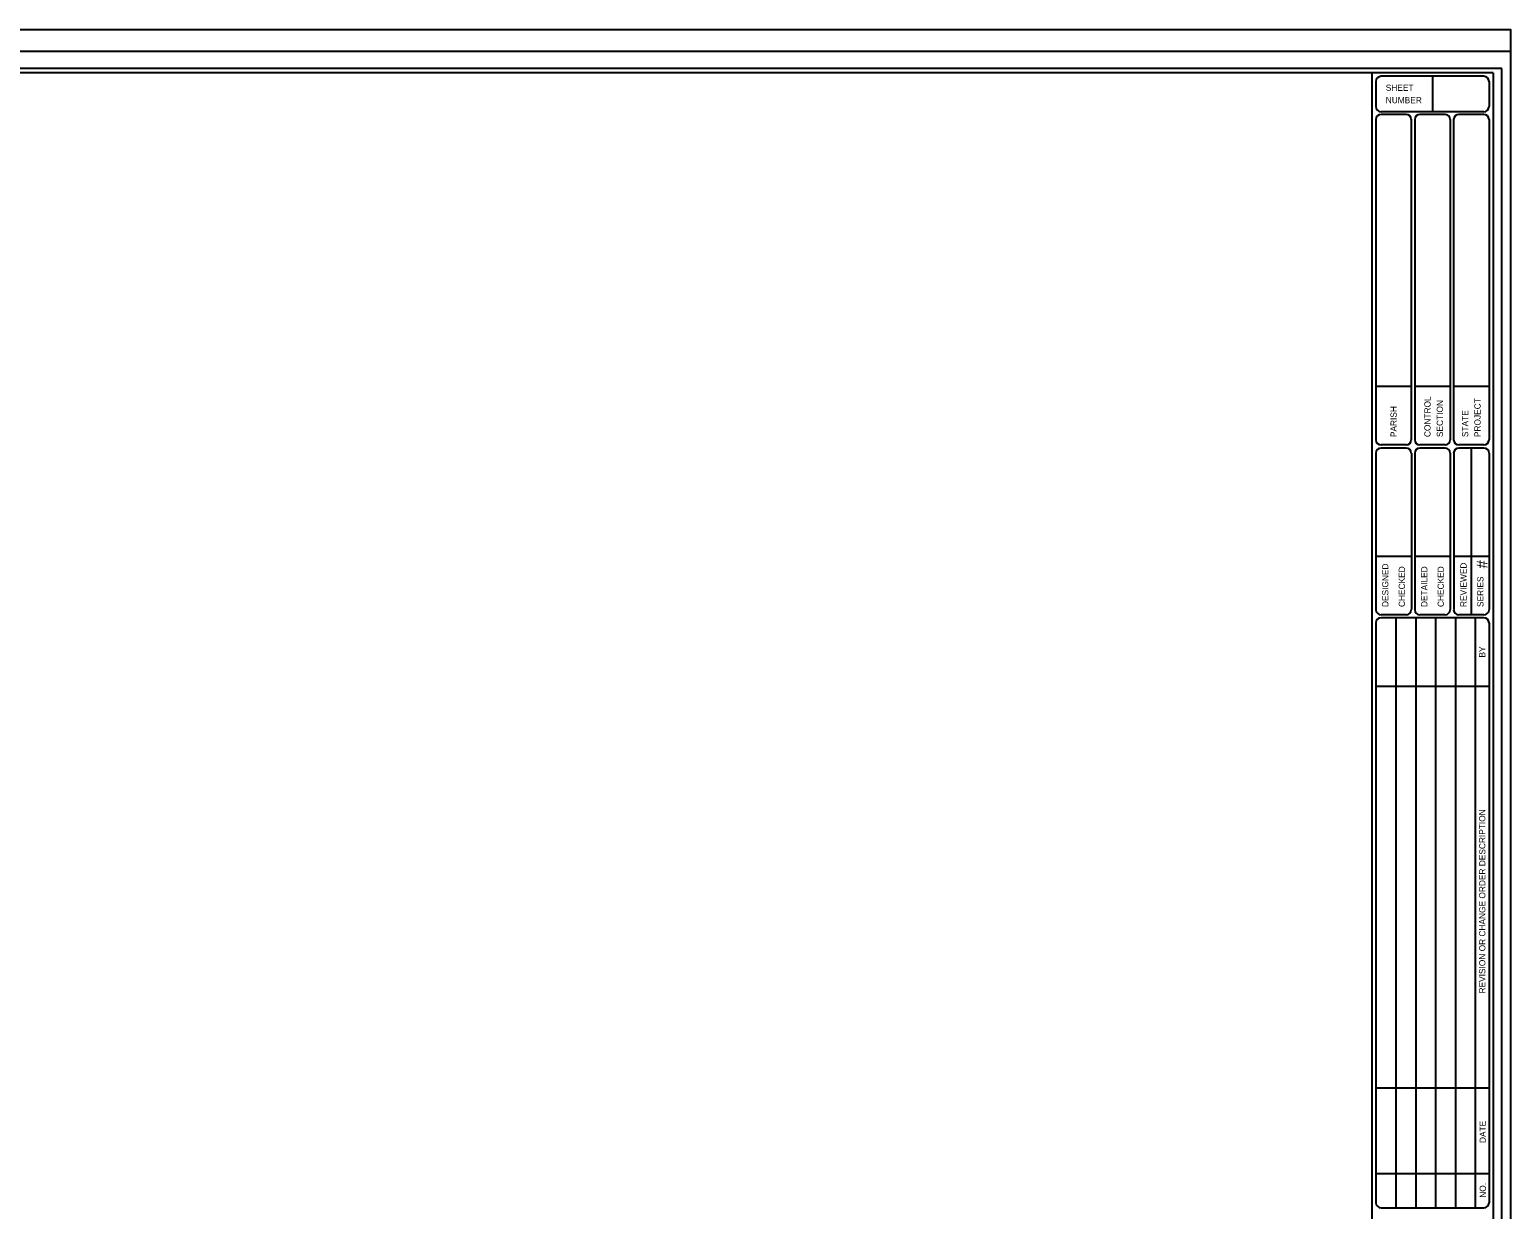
# Model space of a CAD drawing. Extents: x -2.5 to 31.7, y -0.7 to 21.7.
# Drawn here: x 14.59 to 31.7, y 7.86 to 21.5 of the extents above; entities that cross this region are included whole.
import ezdxf

# ---------------------------------------------------------------- set-up
doc = ezdxf.new("R2010")
doc.units = 0
for name, color, linetype in [('Annotation', 7, 'Continuous'), ('Plot Border', 7, 'Continuous'), ('Plot Border 2', 7, 'Continuous'), ('Sheet Border', 7, 'Continuous')]:
    doc.layers.add(name, color=color, linetype=linetype)

msp = doc.modelspace()

# ---------------------------------------------------------------- linework, layer by layer
at = {"layer": 'Plot Border'}
for points in [[(-2.3, 21.5), (31.7, 21.5), (31.7, -0.5), (-2.3, -0.5)], [(31.6, 21.05), (-1.4, 21.05), (-1.4, -0.05), (31.6, -0.05)]]:
    msp.add_lwpolyline(points, close=True, dxfattribs=at)
at = {"layer": 'Plot Border 2'}
msp.add_lwpolyline([(-2.3, 21.25), (31.7, 21.25), (31.7, -0.25), (-2.3, -0.25)], close=True, dxfattribs=at)
at = {"layer": 'Sheet Border'}
for p, q in [((31.5, 21), (0, 21)), ((30.1, 21), (30.1, 0)), ((30.146, 20.901), (30.146, 20.611)), ((31.394, 20.96), (30.206, 20.96)), ((30.8, 20.96), (30.8, 20.551)), ((31.454, 20.901), (31.454, 20.611)), ((31.5, 21), (31.5, 0)), ((31.394, 20.551), (30.206, 20.551)), ((30.146, 20.464), (30.146, 16.754)), ((30.496, 20.52), (30.206, 20.52)), ((30.555, 20.465), (30.555, 16.754)), ((30.595, 20.46), (30.595, 16.759)), ((30.945, 20.52), (30.654, 20.52)), ((31.005, 20.461), (31.005, 16.758)), ((31.044, 20.46), (31.044, 16.759)), ((31.394, 20.52), (31.104, 20.52)), ((31.454, 20.46), (31.454, 16.759)), ((30.555, 17.373), (30.146, 17.373)), ((31.005, 17.373), (30.595, 17.373)), ((31.454, 17.373), (31.044, 17.373)), ((30.146, 16.608), (30.146, 14.796)), ((30.496, 16.699), (30.206, 16.699)), ((30.496, 16.663), (30.206, 16.663)), ((30.556, 16.603), (30.556, 14.796)), ((30.595, 16.608), (30.595, 14.796)), ((30.945, 16.699), (30.654, 16.699)), ((30.946, 16.663), (30.655, 16.663)), ((31.005, 16.603), (31.005, 14.796)), ((31.045, 16.608), (31.045, 14.796)), ((31.394, 16.699), (31.104, 16.699)), ((31.395, 16.663), (31.104, 16.663)), ((31.249, 14.736), (31.249, 16.663)), ((31.454, 16.603), (31.454, 14.796)), ((30.555, 15.41), (30.146, 15.41)), ((31.005, 15.41), (30.595, 15.41)), ((31.454, 15.41), (31.044, 15.41)), ((30.496, 14.736), (30.206, 14.736)), ((30.946, 14.736), (30.655, 14.736)), ((31.395, 14.736), (31.104, 14.736)), ((30.146, 14.643), (30.146, 7.941)), ((31.394, 14.701), (30.206, 14.701)), ((30.376, 14.701), (30.376, 7.882)), ((30.606, 14.701), (30.606, 7.882)), ((30.836, 14.701), (30.836, 7.882)), ((31.065, 14.701), (31.065, 7.882)), ((31.295, 14.701), (31.295, 7.882)), ((31.454, 14.643), (31.454, 7.941)), ((31.454, 13.909), (30.146, 13.909)), ((30.146, 9.269), (31.454, 9.269)), ((30.146, 8.278), (31.454, 8.278)), ((30.206, 7.882), (31.394, 7.882))]:
    msp.add_line(p, q, dxfattribs=at)
for centre, start, end in [((30.206, 20.901), 90, 180), ((31.394, 20.901), 0, 90), ((30.206, 20.61), 180, 270), ((31.394, 20.61), 270, 0), ((30.206, 20.46), 90, 180), ((30.496, 20.46), 0, 90), ((30.655, 20.46), 90, 180), ((30.945, 20.46), 0, 90), ((31.104, 20.46), 90, 180), ((31.394, 20.46), 0, 90), ((30.206, 16.759), 180, 270), ((30.206, 16.604), 90, 180), ((30.496, 16.759), 270, 0), ((30.496, 16.604), 0, 90), ((30.655, 16.759), 180, 270), ((30.655, 16.604), 90, 180), ((30.945, 16.759), 270, 0), ((30.945, 16.604), 0, 90), ((31.104, 16.759), 180, 270), ((31.104, 16.604), 90, 180), ((31.394, 16.759), 270, 0), ((31.395, 16.604), 0, 90), ((30.206, 14.795), 180, 270), ((30.496, 14.795), 270, 0), ((30.655, 14.795), 180, 270), ((30.945, 14.795), 270, 0), ((31.104, 14.795), 180, 270), ((31.395, 14.795), 270, 0), ((30.206, 14.643), 90, 180), ((31.394, 14.643), 0, 90), ((30.206, 7.941), 180, 270), ((31.394, 7.941), 270, 0)]:
    msp.add_arc(centre, 0.0594, start, end, dxfattribs=at)

# ---------------------------------------------------------------- texts
at = {"layer": 'Annotation'}
msp.add_text('#', height=0.128, rotation=90, dxfattribs=at).set_placement((31.437, 15.272))
at = {"layer": 'Sheet Border'}
for s, p in [('SHEET', (30.26, 20.792)), ('NUMBER', (30.26, 20.649))]:
    msp.add_text(s, height=0.072, dxfattribs=at).set_placement(p)
for s, p in [('PARISH', (30.387, 16.79)), ('CONTROL', (30.778, 16.79)), ('SECTION', (30.921, 16.79)), ('PROJECT', (31.356, 16.79)), ('STATE', (31.213, 16.79)), ('DESIGNED', (30.291, 14.826)), ('CHECKED', (30.482, 14.826)), ('DETAILED', (30.741, 14.826)), ('CHECKED', (30.931, 14.826)), ('REVIEWED', (31.194, 14.826)), ('SERIES', (31.389, 14.826)), ('BY', (31.411, 14.242)), ('REVISION OR CHANGE ORDER DESCRIPTION', (31.411, 10.359)), ('DATE', (31.416, 8.631)), ('NO.', (31.417, 7.998))]:
    msp.add_text(s, height=0.072, rotation=90, dxfattribs=at).set_placement(p)

doc.saveas('drawing.dxf')
